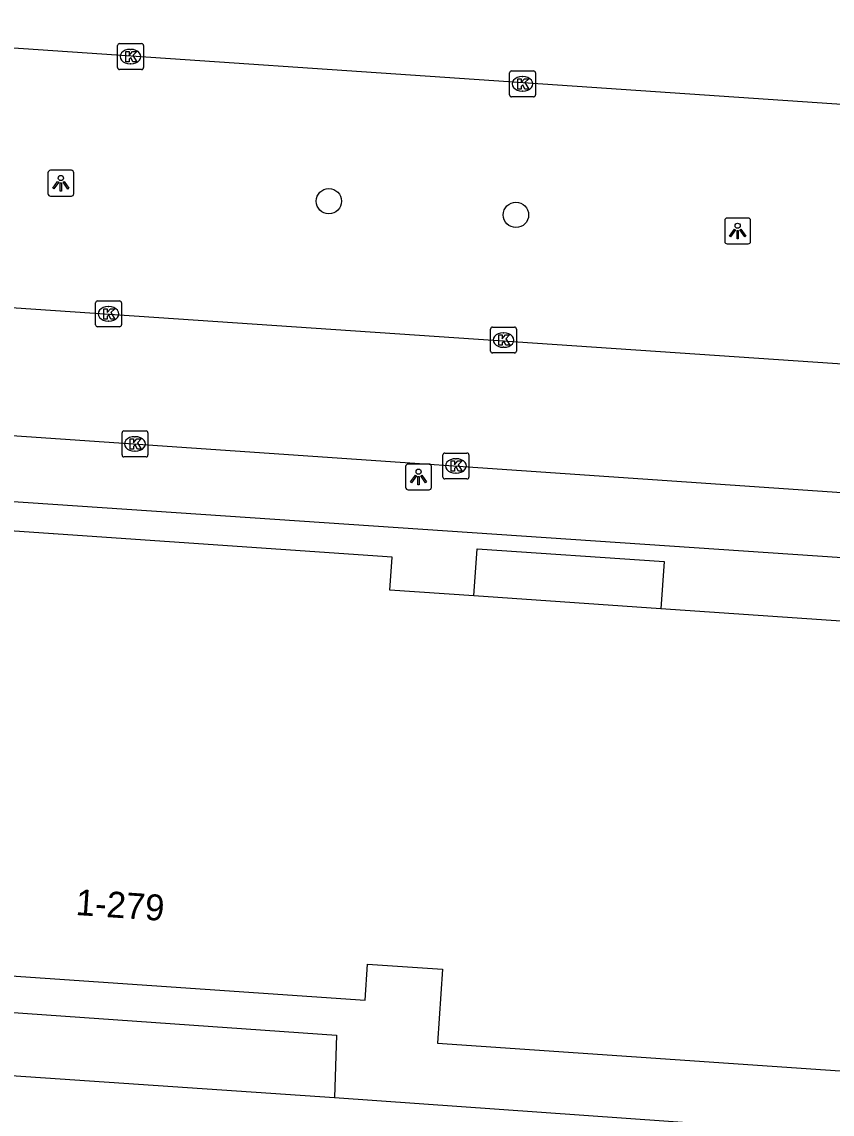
# Model space of a CAD drawing. Extents: x 161848 to 162726, y 385382 to 386521.
# Drawn here: x 161938.84 to 161970.13, y 385419.53 to 385461.69 of the extents above; entities that cross this region are included whole.
import ezdxf

# ---------------------------------------------------------------- set-up
doc = ezdxf.new("R2010")
doc.units = 0
for name, color, linetype in [('IMGEO_Boom', 7, 'Continuous'), ('IMGEO_Groenvoorziening', 7, 'Continuous'), ('IMGEO_Kolk', 7, 'Continuous'), ('IMGEO_Lichtpunt', 7, 'Continuous'), ('IMGEO_Pand', 7, 'Continuous'), ('IMGEO_Pand_nummerreeks', 7, 'Continuous'), ('IMGEO_Rijbaan_lokaal_open', 7, 'Continuous'), ('IMGEO_Voetpad_open', 7, 'Continuous')]:
    doc.layers.add(name, color=color, linetype=linetype)

msp = doc.modelspace()

# ---------------------------------------------------------------- linework, layer by layer
at = {"layer": 'IMGEO_Boom'}
for centre in [(161950.696, 385454.767), (161957.919, 385454.237)]:
    msp.add_circle(centre, 0.489, dxfattribs=at)
at = {"layer": 'IMGEO_Groenvoorziening'}
msp.add_lwpolyline([(161918.939, 385422.345), (161950.913, 385420.167)], dxfattribs=at)
at = {"layer": 'IMGEO_Kolk'}
for p, q in [((161942.616, 385460.848), (161943.468, 385460.848)), ((161942.541, 385459.922), (161942.541, 385460.774)), ((161943.029, 385460.628), (161943.054, 385460.628)), ((161943.542, 385460.774), (161943.542, 385459.922)), ((161943.052, 385460.068), (161943.027, 385460.068)), ((161943.468, 385459.848), (161942.616, 385459.848)), ((161957.673, 385458.869), (161957.673, 385459.721)), ((161957.748, 385459.795), (161958.6, 385459.795)), ((161958.161, 385459.575), (161958.186, 385459.575)), ((161958.674, 385459.721), (161958.674, 385458.869)), ((161958.6, 385458.795), (161957.748, 385458.795)), ((161958.184, 385459.015), (161958.159, 385459.015)), ((161941.689, 385449.992), (161941.689, 385450.844)), ((161941.764, 385450.918), (161942.616, 385450.918)), ((161942.69, 385450.844), (161942.69, 385449.992)), ((161942.177, 385450.698), (161942.202, 385450.698)), ((161942.616, 385449.918), (161941.764, 385449.918)), ((161942.2, 385450.138), (161942.175, 385450.138)), ((161957.012, 385449.907), (161957.864, 385449.907)), ((161956.937, 385448.981), (161956.937, 385449.833)), ((161957.425, 385449.687), (161957.45, 385449.687)), ((161957.938, 385449.833), (161957.938, 385448.981)), ((161957.448, 385449.127), (161957.423, 385449.127)), ((161957.864, 385448.907), (161957.012, 385448.907)), ((161942.71, 385444.97), (161942.71, 385445.822)), ((161942.785, 385445.896), (161943.637, 385445.896)), ((161943.198, 385445.676), (161943.223, 385445.676)), ((161943.711, 385445.822), (161943.711, 385444.97)), ((161943.637, 385444.896), (161942.785, 385444.896)), ((161943.221, 385445.116), (161943.196, 385445.116)), ((161955.102, 385444.12), (161955.102, 385444.972)), ((161955.177, 385445.046), (161956.029, 385445.046)), ((161955.59, 385444.826), (161955.615, 385444.826)), ((161956.103, 385444.972), (161956.103, 385444.12)), ((161956.029, 385444.046), (161955.177, 385444.046)), ((161955.613, 385444.266), (161955.588, 385444.266))]:
    msp.add_line(p, q, dxfattribs=at)
for points in [[(161942.616, 385460.848), (161943.468, 385460.848)], [(161942.541, 385459.922), (161942.541, 385460.774)], [(161942.862, 385460.548), (161942.985, 385460.548), (161942.985, 385460.397), (161943.115, 385460.548), (161943.279, 385460.548), (161943.133, 385460.397), (161943.286, 385460.148), (161943.134, 385460.148), (161943.049, 385460.312), (161942.985, 385460.245), (161942.985, 385460.148), (161942.862, 385460.148), (161942.862, 385460.548)], [(161943.542, 385460.774), (161943.542, 385459.922)], [(161943.468, 385459.848), (161942.616, 385459.848)], [(161957.673, 385458.869), (161957.673, 385459.721)], [(161957.748, 385459.795), (161958.6, 385459.795)], [(161958.674, 385459.721), (161958.674, 385458.869)], [(161957.994, 385459.495), (161958.117, 385459.495), (161958.117, 385459.344), (161958.247, 385459.495), (161958.411, 385459.495), (161958.265, 385459.344), (161958.418, 385459.095), (161958.266, 385459.095), (161958.181, 385459.259), (161958.117, 385459.192), (161958.117, 385459.095), (161957.994, 385459.095), (161957.994, 385459.495)], [(161958.6, 385458.795), (161957.748, 385458.795)], [(161941.689, 385449.992), (161941.689, 385450.844)], [(161941.764, 385450.918), (161942.616, 385450.918)], [(161942.69, 385450.844), (161942.69, 385449.992)], [(161942.01, 385450.618), (161942.133, 385450.618), (161942.133, 385450.467), (161942.263, 385450.618), (161942.427, 385450.618), (161942.281, 385450.467), (161942.434, 385450.218), (161942.282, 385450.218), (161942.197, 385450.382), (161942.133, 385450.315), (161942.133, 385450.218), (161942.01, 385450.218), (161942.01, 385450.618)], [(161942.616, 385449.918), (161941.764, 385449.918)], [(161957.012, 385449.907), (161957.864, 385449.907)], [(161956.937, 385448.981), (161956.937, 385449.833)], [(161957.258, 385449.607), (161957.381, 385449.607), (161957.381, 385449.456), (161957.511, 385449.607), (161957.675, 385449.607), (161957.529, 385449.456), (161957.682, 385449.207), (161957.53, 385449.207), (161957.445, 385449.371), (161957.381, 385449.304), (161957.381, 385449.207), (161957.258, 385449.207), (161957.258, 385449.607)], [(161957.938, 385449.833), (161957.938, 385448.981)], [(161957.864, 385448.907), (161957.012, 385448.907)], [(161942.71, 385444.97), (161942.71, 385445.822)], [(161942.785, 385445.896), (161943.637, 385445.896)], [(161943.711, 385445.822), (161943.711, 385444.97)], [(161943.031, 385445.596), (161943.154, 385445.596), (161943.154, 385445.445), (161943.284, 385445.596), (161943.448, 385445.596), (161943.302, 385445.445), (161943.455, 385445.196), (161943.303, 385445.196), (161943.218, 385445.36), (161943.154, 385445.293), (161943.154, 385445.196), (161943.031, 385445.196), (161943.031, 385445.596)], [(161943.637, 385444.896), (161942.785, 385444.896)], [(161955.102, 385444.12), (161955.102, 385444.972)], [(161955.177, 385445.046), (161956.029, 385445.046)], [(161956.103, 385444.972), (161956.103, 385444.12)], [(161955.423, 385444.746), (161955.546, 385444.746), (161955.546, 385444.595), (161955.676, 385444.746), (161955.84, 385444.746), (161955.694, 385444.595), (161955.847, 385444.346), (161955.695, 385444.346), (161955.61, 385444.51), (161955.546, 385444.443), (161955.546, 385444.346), (161955.423, 385444.346), (161955.423, 385444.746)], [(161956.029, 385444.046), (161955.177, 385444.046)]]:
    msp.add_lwpolyline(points, dxfattribs=at)
for centre, start, end in [((161942.618, 385460.772), 91.552, 178.448), ((161942.618, 385460.772), 91.552, 178.448), ((161943.466, 385460.772), 1.552, 88.448), ((161943.466, 385460.772), 1.552, 88.448), ((161942.618, 385459.924), 181.552, 268.448), ((161942.618, 385459.924), 181.552, 268.448), ((161943.466, 385459.924), 271.552, 358.448), ((161943.466, 385459.924), 271.552, 358.448), ((161957.75, 385459.719), 91.552, 178.448), ((161957.75, 385459.719), 91.552, 178.448), ((161958.598, 385459.719), 1.552, 88.448), ((161958.598, 385459.719), 1.552, 88.448), ((161957.75, 385458.871), 181.552, 268.448), ((161957.75, 385458.871), 181.552, 268.448), ((161958.598, 385458.871), 271.552, 358.448), ((161958.598, 385458.871), 271.552, 358.448), ((161941.766, 385450.842), 91.552, 178.448), ((161941.766, 385450.842), 91.552, 178.448), ((161942.614, 385450.842), 1.552, 88.448), ((161942.614, 385450.842), 1.552, 88.448), ((161941.766, 385449.994), 181.552, 268.448), ((161941.766, 385449.994), 181.552, 268.448), ((161942.614, 385449.994), 271.552, 358.448), ((161942.614, 385449.994), 271.552, 358.448), ((161957.014, 385449.831), 91.552, 178.448), ((161957.014, 385449.831), 91.552, 178.448), ((161957.862, 385449.831), 1.552, 88.448), ((161957.862, 385449.831), 1.552, 88.448), ((161957.014, 385448.983), 181.552, 268.448), ((161957.014, 385448.983), 181.552, 268.448), ((161957.862, 385448.983), 271.552, 358.448), ((161957.862, 385448.983), 271.552, 358.448), ((161942.787, 385445.82), 91.552, 178.448), ((161942.787, 385445.82), 91.552, 178.448), ((161943.635, 385445.82), 1.552, 88.448), ((161943.635, 385445.82), 1.552, 88.448), ((161942.787, 385444.972), 181.552, 268.448), ((161942.787, 385444.972), 181.552, 268.448), ((161943.635, 385444.972), 271.552, 358.448), ((161943.635, 385444.972), 271.552, 358.448), ((161955.179, 385444.97), 91.552, 178.448), ((161955.179, 385444.97), 91.552, 178.448), ((161956.027, 385444.97), 1.552, 88.448), ((161956.027, 385444.97), 1.552, 88.448), ((161955.179, 385444.122), 181.552, 268.448), ((161955.179, 385444.122), 181.552, 268.448), ((161956.027, 385444.122), 271.552, 358.448), ((161956.027, 385444.122), 271.552, 358.448)]:
    msp.add_arc(centre, 0.0765, start, end, dxfattribs=at)
for centre, major_axis, ratio, start_param, end_param in [((161943.028, 385460.348), (-0.387, 0.002), 0.722429, 4.712389, 7.853982), ((161943.053, 385460.348), (-0.39, 0.002), 0.717154, 1.570796, 4.712389), ((161958.16, 385459.295), (-0.387, 0.002), 0.722429, 4.712389, 7.853982), ((161958.185, 385459.295), (-0.39, 0.002), 0.717154, 1.570796, 4.712389), ((161942.176, 385450.418), (-0.387, 0.002), 0.722429, 4.712389, 7.853982), ((161942.201, 385450.418), (-0.39, 0.002), 0.717154, 1.570796, 4.712389), ((161957.424, 385449.407), (-0.387, 0.002), 0.722429, 4.712389, 7.853982), ((161957.449, 385449.407), (-0.39, 0.002), 0.717154, 1.570796, 4.712389), ((161943.197, 385445.396), (-0.387, 0.002), 0.722429, 4.712389, 7.853982), ((161943.222, 385445.396), (-0.39, 0.002), 0.717154, 1.570796, 4.712389), ((161955.589, 385444.546), (-0.387, 0.002), 0.722429, 4.712389, 7.853982), ((161955.614, 385444.546), (-0.39, 0.002), 0.717154, 1.570796, 4.712389)]:
    msp.add_ellipse(centre, major_axis=major_axis, ratio=ratio, start_param=start_param, end_param=end_param, dxfattribs=at)
at = {"layer": 'IMGEO_Lichtpunt'}
for p, q in [((161939.852, 385455.864), (161939.852, 385455.057)), ((161939.852, 385455.864), (161939.852, 385455.057)), ((161940.754, 385455.959), (161939.946, 385455.959)), ((161940.754, 385455.959), (161939.946, 385455.959)), ((161940.848, 385455.057), (161940.848, 385455.864)), ((161940.848, 385455.057), (161940.848, 385455.864)), ((161939.946, 385454.963), (161940.754, 385454.963)), ((161939.946, 385454.963), (161940.754, 385454.963)), ((161966.881, 385454.117), (161966.073, 385454.117)), ((161966.881, 385454.117), (161966.073, 385454.117)), ((161965.979, 385454.022), (161965.979, 385453.215)), ((161965.979, 385454.022), (161965.979, 385453.215)), ((161966.975, 385453.215), (161966.975, 385454.022)), ((161966.975, 385453.215), (161966.975, 385454.022)), ((161966.073, 385453.121), (161966.881, 385453.121)), ((161966.073, 385453.121), (161966.881, 385453.121)), ((161953.661, 385444.527), (161953.661, 385443.72)), ((161953.661, 385444.527), (161953.661, 385443.72)), ((161954.563, 385444.622), (161953.755, 385444.622)), ((161954.563, 385444.622), (161953.755, 385444.622)), ((161954.657, 385443.72), (161954.657, 385444.527)), ((161954.657, 385443.72), (161954.657, 385444.527)), ((161953.755, 385443.626), (161954.563, 385443.626)), ((161953.755, 385443.626), (161954.563, 385443.626))]:
    msp.add_line(p, q, dxfattribs=at)
for points in [[(161940.226, 385455.528), (161940.265, 385455.5), (161940.077, 385455.238), (161940.039, 385455.265), (161940.226, 385455.528)], [(161940.328, 385455.48), (161940.375, 385455.48), (161940.375, 385455.158), (161940.328, 385455.158), (161940.328, 385455.48)], [(161940.438, 385455.5), (161940.476, 385455.527), (161940.663, 385455.265), (161940.624, 385455.237), (161940.438, 385455.5)], [(161966.353, 385453.686), (161966.392, 385453.658), (161966.204, 385453.396), (161966.166, 385453.423), (161966.353, 385453.686)], [(161966.565, 385453.658), (161966.603, 385453.685), (161966.79, 385453.423), (161966.751, 385453.395), (161966.565, 385453.658)], [(161966.455, 385453.638), (161966.502, 385453.638), (161966.502, 385453.316), (161966.455, 385453.316), (161966.455, 385453.638)], [(161954.035, 385444.191), (161954.074, 385444.163), (161953.886, 385443.901), (161953.848, 385443.928), (161954.035, 385444.191)], [(161954.137, 385444.143), (161954.184, 385444.143), (161954.184, 385443.821), (161954.137, 385443.821), (161954.137, 385444.143)], [(161954.247, 385444.163), (161954.285, 385444.19), (161954.472, 385443.928), (161954.433, 385443.9), (161954.247, 385444.163)]]:
    msp.add_lwpolyline(points, dxfattribs=at)
for centre in [(161940.351, 385455.662), (161966.478, 385453.82), (161954.16, 385444.325)]:
    msp.add_circle(centre, 0.0994, dxfattribs=at)
for centre, start, end in [((161939.946, 385455.864), 90, 180), ((161939.946, 385455.864), 90, 180), ((161940.754, 385455.864), 0, 90), ((161940.754, 385455.864), 0, 90), ((161939.946, 385455.057), 180, 270), ((161939.946, 385455.057), 180, 270), ((161940.754, 385455.057), 270, 0), ((161940.754, 385455.057), 270, 360), ((161966.073, 385454.022), 90, 180), ((161966.073, 385454.022), 90, 180), ((161966.881, 385454.022), 0, 90), ((161966.881, 385454.022), 0, 90), ((161966.073, 385453.215), 180, 270), ((161966.073, 385453.215), 180, 270), ((161966.881, 385453.215), 270, 0), ((161966.881, 385453.215), 270, 360), ((161953.755, 385444.527), 90, 180), ((161953.755, 385444.527), 90, 180), ((161954.563, 385444.527), 0, 90), ((161954.563, 385444.527), 0, 90), ((161953.755, 385443.72), 180, 270), ((161953.755, 385443.72), 180, 270), ((161954.563, 385443.72), 270, 0), ((161954.563, 385443.72), 270, 360)]:
    msp.add_arc(centre, 0.0946, start, end, dxfattribs=at)
at = {"layer": 'IMGEO_Pand'}
for points in [[(161956.298, 385439.531), (161953.055, 385439.753), (161953.142, 385441.032), (161926.96, 385442.825)], [(161963.511, 385439.037), (161956.298, 385439.531)], [(161977.598, 385438.072), (161963.511, 385439.037)], [(161937.676, 385424.911), (161952.097, 385423.924), (161952.193, 385425.321), (161955.086, 385425.123), (161954.89, 385422.261), (161988.226, 385419.978)]]:
    msp.add_lwpolyline(points, dxfattribs=at)
at = {"layer": 'IMGEO_Rijbaan_lokaal_open'}
for points in [[(161979.068, 385448.168), (161979.046, 385447.88), (161972.608, 385448.334), (161923.043, 385451.687), (161923.766, 385461.69), (161973.336, 385458.313), (161979.773, 385457.856), (161979.742, 385457.49)], [(161927.586, 385446.469), (161982.306, 385442.712)]]:
    msp.add_lwpolyline(points, dxfattribs=at)
at = {"layer": 'IMGEO_Voetpad_open'}
for points in [[(161979.088, 385440.424), (161931.458, 385443.642)], [(161956.298, 385439.531), (161956.423, 385441.348), (161963.636, 385440.854), (161963.511, 385439.037)], [(161937.585, 385423.515), (161950.994, 385422.569), (161950.913, 385420.167)], [(161950.913, 385420.167), (161984.51, 385417.786)]]:
    msp.add_lwpolyline(points, dxfattribs=at)

# ---------------------------------------------------------------- texts
at = {"layer": 'IMGEO_Pand_nummerreeks'}
msp.add_text('1-279', height=1, rotation=356.0853, dxfattribs=at).set_placement((161940.9, 385427.216))

doc.saveas('drawing.dxf')
